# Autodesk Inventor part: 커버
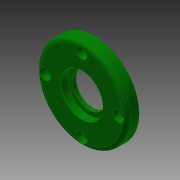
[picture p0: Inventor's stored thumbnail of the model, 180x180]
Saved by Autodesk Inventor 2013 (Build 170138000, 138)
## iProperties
Created: 2019-09
Part Number: 커버
Material: 알루미늄 6061
Document SubType Name: Modeling
Designer: mduedu
Density: 1 g/cm^3
Author: mduedu
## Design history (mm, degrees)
sketch "스케치1"
  geometry: L1 (-32, -32)-(32, -32); L2 (32, -32)-(32, 32); L3 (32, 32)-(-32, 32); L4 (-32, 32)-(-32, -32); L5 (-32, -32)-(32, 32); L6 (32, -32)-(-32, 32); C1 r 32 at (0, 0); 1 further point
  constraints: 12 end point, 2 midpoint, 2 parallel, 1 centre point, 1 coincident, 1 horizontal, 1 perpendicular, 1 tangent
  dimensions: "d44" = 64 distance of L3.end L2.end; "d45" = 64 distance of L2.end L1.end
extrude "돌출1" new body sketch "스케치1" distance "d1" = 9; taper "d2" = 0 deg
sketch "스케치5"
  geometry: C1 r 32 at (0, 0) reference; C2 r 21 at (0, 0)
  constraints: 1 centre point, 1 coincident
  dimensions: "d57" = 42 diameter of C2
extrude "돌출3" join sketch "스케치5" distance "d58" = 3; taper "d59" = 0 deg
sketch "스케치6"
  geometry: L1 (-9, 15)-(-3.8, 15); L2 (-3.8, 15)-(-3.8, 12); L3 (-3.8, 12)-(-1, 12); L4 (-1, 12)-(-1, 18.5); L5 (-1, 18.5)-(3, 18.5); L6 (-9, 32)-(-9, -32) reference; L7 (3, -21)-(3, 21) reference; L8 (-9, 0)-(3, 0); 1 further point
  constraints: 12 end point, 3 parallel, 2 midpoint, 2 point on line, 1 horizontal, 1 perpendicular
  dimensions: "d60" = 4 distance of L4.end L5.end; "d61" = 37 diameter of L5.end L8; "d62" = 24 diameter of L3 L8; "d63" = 30 diameter of L1 L8; "d65" = 5.2 distance of L1.start L1.end
revolve "회전1" sketch "스케치6" stored, may be unused: angle "d66" = 90 deg
fillet "모깎기1" dims "d24" = 3
fillet "모깎기2" dims "d25" = 3
chamfer "모따기1" distance "d27" = 0.5; stored, may be unused: second distance "d28" = 2, angle "d29" = 30 deg
chamfer "모따기2" distance "d30" = 1; stored, may be unused: second distance "d31" = 2, angle "d32" = 30 deg
sketch "스케치4"
  geometry: C1 r 15.289 at (0, 0) reference; A1 r 26 centre (0, 0) between (0, 26) and (26, 0); 3 further points
  constraints: 4 point on circle, 2 horizontal alignment, 2 vertical alignment, 1 centre point, 1 coincident
  dimensions: "d67" = 52 diameter of A1
hole "구멍4" sketch "스케치4" at (0, 26), (26, 0), (0, -26), (-26, 0) diameter "d49" = 4.5; stored, may be unused: countersink angle "d53" = 90 deg, drill point angle "d55" = 118 deg; dims "d50" = 6, "d51" = 8, "d52" = 4.4, "d54" = 8
node "솔리드1"
